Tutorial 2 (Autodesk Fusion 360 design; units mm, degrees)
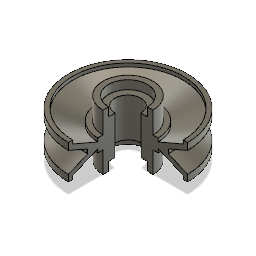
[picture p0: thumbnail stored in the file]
sketch "Sketch1" plane through (0, 0, 0) normal (0, 0, 1) x axis (1, 0, 0)
  line L1 (0, 0) -> (70.0414, 0)
  line L2 (0, 36.2287) -> (0, 0)
  line L3 (15, 22.5) -> (15, 0)
  line L4 (22.5, 22.5) -> (15, 22.5)
  line L5 (22.5, 32.5) -> (22.5, 22.5)
  line L6 (29, 32.5) -> (22.5, 32.5)
  line L7 (29, 7.5) -> (29, 32.5)
  line L8 (35, 7.5) -> (29, 7.5)
  line L9 (35, 3.5) -> (35, 7.5)
  line L10 (64, 16) -> (35, 3.5)
  line L11 (64, 20) -> (64, 16)
  line L12 (69, 20) -> (64, 20)
  line L13 (69, 12) -> (69, 20)
  line L14 (46.96, 2.5) -> (69, 12)
  line L15 (46.96, 0) -> (46.96, 2.5)
  line L16 (22.5, -32.5) -> (22.5, -22.5)
  line L17 (29, -7.5) -> (29, -32.5)
  line L18 (29, -32.5) -> (22.5, -32.5)
  line L19 (15, -22.5) -> (15, 0)
  line L20 (22.5, -22.5) -> (15, -22.5)
  line L21 (46.96, -2.5) -> (69, -12)
  line L22 (69, -20) -> (64, -20)
  line L23 (64, -20) -> (64, -16)
  line L24 (64, -16) -> (35, -3.5)
  line L25 (35, -7.5) -> (29, -7.5)
  line L26 (46.96, 0) -> (46.96, -2.5)
  line L27 (35, -3.5) -> (35, -7.5)
  line L28 (69, -12) -> (69, -20)
  point P1 (0, 0)
  point P3 (0, 0)
  point P5 (15, 0)
  point P18 (46.96, 0)
  point P2 (70.0414, 0)
  point P21 (70.0414, 0)
  point P20 (15, 0)
  point P6 (15, 22.5)
  point P24 (15, -22.5)
  point P7 (22.5, 22.5)
  point P22 (22.5, -22.5)
  point P8 (22.5, 32.5)
  point P19 (22.5, -32.5)
  point P9 (29, 32.5)
  point P25 (29, -32.5)
  point P10 (29, 7.5)
  point P23 (29, -7.5)
  point P11 (35, 7.5)
  point P28 (35, -7.5)
  point P12 (35, 3.5)
  point P27 (35, -3.5)
  point P13 (64, 16)
  point P26 (64, -16)
  point P14 (64, 20)
  point P32 (64, -20)
  point P15 (69, 20)
  point P33 (69, -20)
  point P16 (69, 12)
  point P31 (69, -12)
  point P17 (46.96, 2.5)
  point P30 (46.96, -2.5)
  point P29 (46.96, 0)
  coincident P1 P3
  horizontal L1
  perpendicular L1 L2
  coincident L1 P5
  perpendicular L1 L3
  perpendicular L3 L4
  perpendicular L4 L5
  perpendicular L5 L6
  perpendicular L6 L7
  perpendicular L7 L8
  perpendicular L8 L9
  vertical L11
  perpendicular L11 L12
  perpendicular L12 L13
  parallel L10 L14
  coincident L1 P18
  perpendicular L1 L15
  symmetric P2 L1 P21
  symmetric L1 P5 P20
  symmetric L1 P6 P24
  symmetric L1 P7 P22
  symmetric L1 P8 P19
  symmetric L1 P9 P25
  symmetric L1 P10 P23
  symmetric L1 P11 P28
  symmetric L1 P12 P27
  symmetric L1 P13 P26
  symmetric L1 P14 P32
  symmetric L1 P15 P33
  symmetric L1 P16 P31
  symmetric L1 P17 P30
  symmetric L1 P18 P29
  dimension "d1" distance P6 P24 = 45
  dimension "d2" distance P19 P22 = 10
  dimension "d3" distance P11 P12 = 4
  dimension "d4" distance P9 P10 = 25
  dimension "d5" distance P23 P28 = 6
  dimension "d6" distance P17 P30 = 5
  dimension "d7" distance P13 P14 = 4
  dimension "d8" distance P15 P16 = 8
  dimension "d9" distance L12 L22 = 40
  dimension "d10" = 30
  dimension "d11" = 45
  dimension "d12" = 58
  dimension "d13" = 128
  dimension "d14" = 138
revolve "Revolve1" sketch "Sketch1" AlongAngle -270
